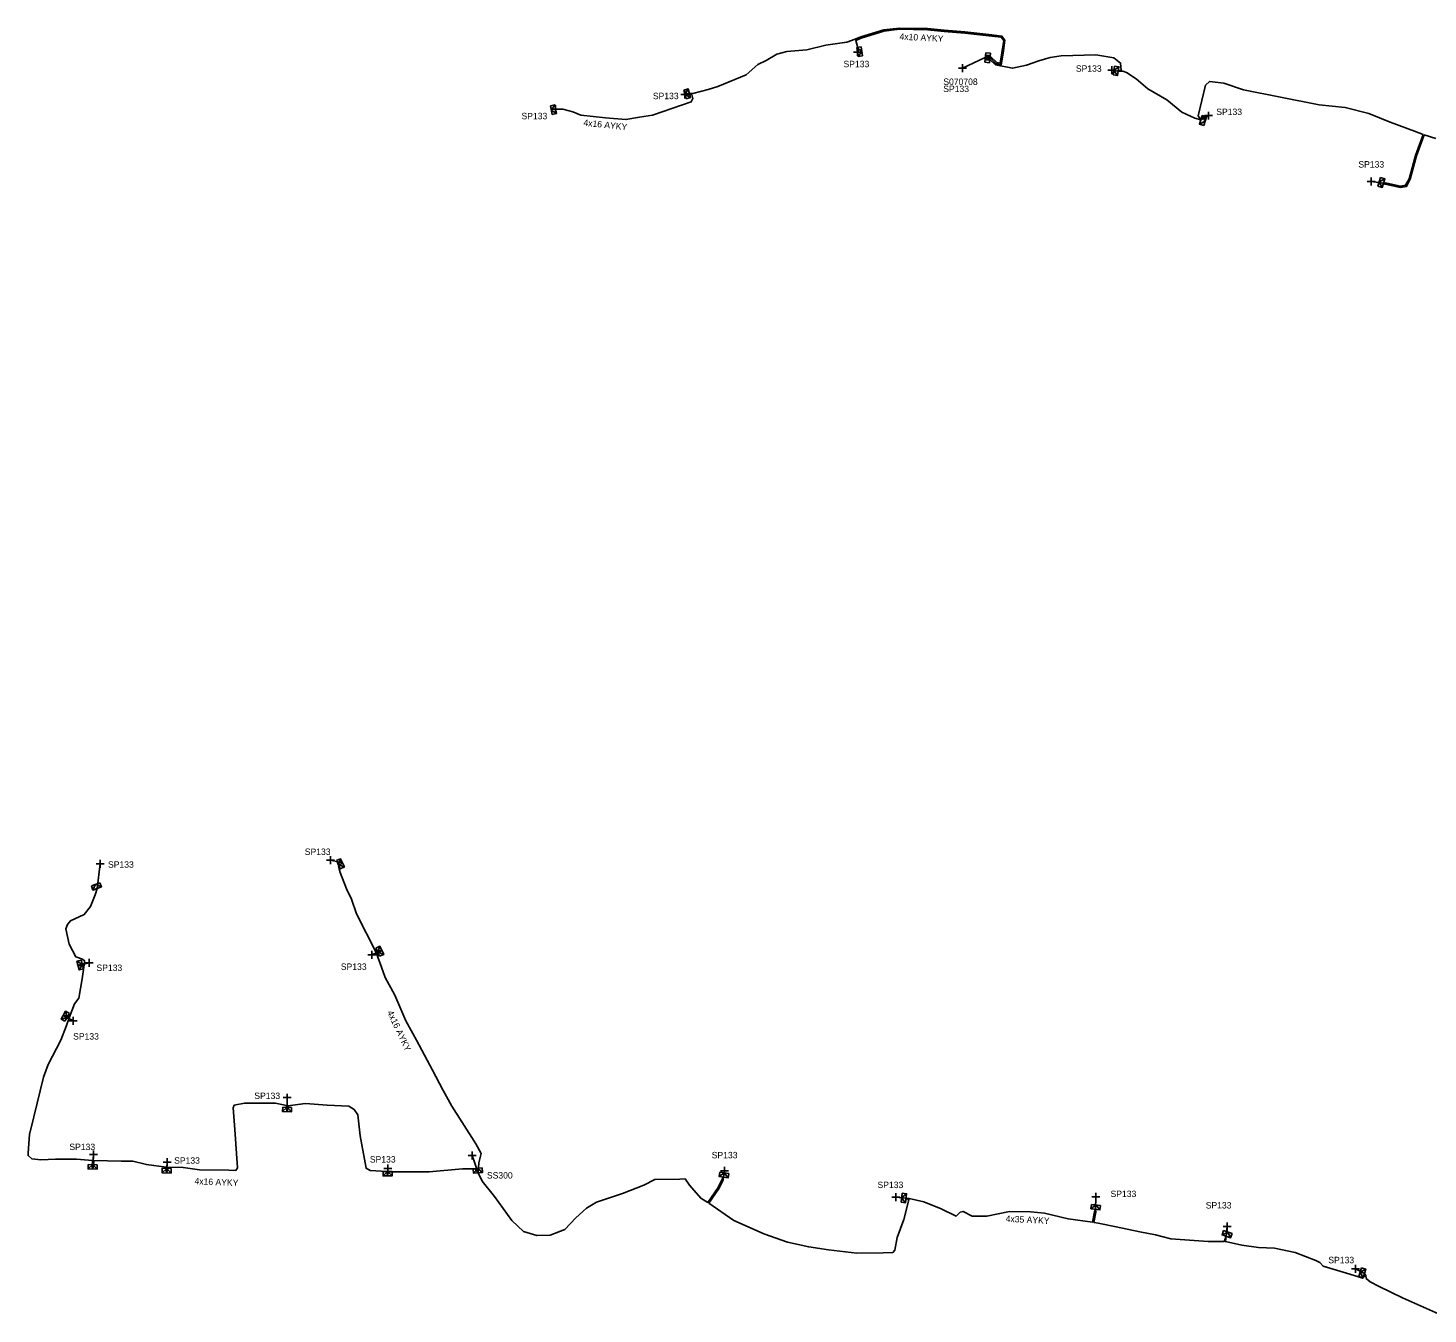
# Model space of a CAD drawing. Extents: x -763093 to -760976, y -1155572 to -1152009.
# Drawn here: x -763081 to -762862.9, y -1153648.9 to -1153448.5 of the extents above; entities that cross this region are included whole.
import ezdxf

# ---------------------------------------------------------------- set-up
doc = ezdxf.new("R2010")
doc.units = 0
for name, color, linetype in [('Vrstva 1', 7, 'Continuous'), ('Vrstva 28', 7, 'Continuous'), ('Vrstva 29', 7, 'Continuous'), ('Vrstva 30', 7, 'Continuous'), ('Vrstva 31', 7, 'Continuous'), ('Vrstva 33', 7, 'Continuous'), ('Vrstva 34', 7, 'Continuous'), ('Vrstva 5', 7, 'Continuous'), ('Vrstva 52', 7, 'Continuous'), ('Vrstva 54', 7, 'Continuous'), ('Vrstva 59', 7, 'Continuous'), ('Vrstva 6', 7, 'Continuous'), ('Vrstva 8', 7, 'Continuous'), ('Vrstva 9', 7, 'Continuous')]:
    doc.layers.add(name, color=color, linetype=linetype)

# ---------------------------------------------------------------- blocks, each defined once
blk = doc.blocks.new('NN800')
at = {"layer": 'Vrstva 1'}
for points in [[(-0.44, 0.44), (0.44, -0.44)], [(-0.44, -0.44), (0.44, 0.44)]]:
    blk.add_lwpolyline(points, dxfattribs=at)
blk = doc.blocks.new('NN620')
at = {"layer": 'Vrstva 8'}
for points in [[(0.75, 0), (-0.75, 0)], [(-0.75, 0), (-0.75, -0.75)], [(0.75, -0.75), (0.75, 0)], [(-0.75, -0.75), (0.75, -0.75)], [(0.37, -0.18), (-0.38, -0.18)], [(-0.38, -0.18), (-0.38, -0.56)], [(-0.38, -0.56), (0.37, -0.56)], [(0.32, -0.23), (-0.33, -0.23)], [(-0.33, -0.23), (-0.33, -0.51)], [(-0.33, -0.51), (0.32, -0.51)], [(0.27, -0.27), (-0.28, -0.27)], [(-0.28, -0.27), (-0.28, -0.46)], [(-0.28, -0.46), (0.27, -0.46)], [(0.23, -0.32), (-0.23, -0.32)], [(-0.23, -0.32), (-0.23, -0.42)], [(-0.23, -0.42), (0.23, -0.42)], [(-0.19, -0.37), (0.19, -0.37)], [(0.23, -0.42), (0.23, -0.32)], [(0.27, -0.46), (0.27, -0.27)], [(0.32, -0.51), (0.32, -0.23)], [(0.37, -0.56), (0.37, -0.18)]]:
    blk.add_lwpolyline(points, dxfattribs=at)
blk = doc.blocks.new('NN630')
at = {"layer": 'Vrstva 9'}
for points in [[(0, -0.7), (-0.7, 0)], [(-0.7, -0.7), (-0.7, 0), (0.7, 0), (0.7, -0.7)], [(-0.7, -0.7), (0.7, -0.7)], [(0, -0.7), (0.7, 0)]]:
    blk.add_lwpolyline(points, dxfattribs=at)

msp = doc.modelspace()

# ---------------------------------------------------------------- linework, layer by layer
at = {"layer": 'Vrstva 5'}
for points in [[(-762931.07, -1153453.19), (-762930.16, -1153454.05), (-762929.37, -1153454.21), (-762929.06, -1153452.4), (-762928.79, -1153450.38), (-762929.28, -1153449.75), (-762930.82, -1153449.56), (-762935.05, -1153449.08), (-762938.25, -1153448.81), (-762940.86, -1153448.58), (-762945.22, -1153448.48), (-762947.69, -1153448.75), (-762951.27, -1153449.86), (-762952.11, -1153450.24), (-762953.44, -1153450.68), (-762956.69, -1153451.17), (-762959.69, -1153451.89), (-762962.76, -1153452.14), (-762964.36, -1153452.58), (-762965.98, -1153453.56), (-762967.3, -1153454.18), (-762969.12, -1153455.76), (-762973.54, -1153457.62), (-762975.04, -1153458.08), (-762977.41, -1153458.69), (-762977.97, -1153458.66)], [(-762861.65, -1153465.71), (-762863.46, -1153465.15), (-762864.64, -1153468.4), (-762865.64, -1153472.04), (-762866.22, -1153473.17), (-762867.16, -1153473.31), (-762869.54, -1153472.82), (-762869.8, -1153472.66), (-762869.51, -1153472.62), (-762867.16, -1153473.11), (-762866.36, -1153472.99), (-762865.82, -1153471.96), (-762864.84, -1153468.34), (-762863.65, -1153465.08), (-762864.98, -1153464.54), (-762868.79, -1153463.13), (-762872.07, -1153461.79), (-762875.79, -1153460.85), (-762879.82, -1153460.46), (-762885.84, -1153459.27), (-762891.63, -1153458.09), (-762894.67, -1153457.09), (-762896.93, -1153456.81), (-762897.52, -1153457.38), (-762898.67, -1153462.16), (-762898.27, -1153462.79), (-762899.18, -1153462.52), (-762901.25, -1153461.62), (-762903.58, -1153459.69), (-762906.53, -1153457.94), (-762908.34, -1153456.41), (-762909.87, -1153455.42), (-762910.45, -1153455.22), (-762911.13, -1153455.21), (-762910.68, -1153455.05), (-762910.78, -1153453.95), (-762911.83, -1153453.15), (-762914.64, -1153452.64), (-762920.01, -1153452.82), (-762921.76, -1153453.1), (-762923.53, -1153453.58), (-762925.45, -1153454.26), (-762927.61, -1153454.75), (-762930.26, -1153454.23), (-762931.1, -1153453.43)], [(-763010.89, -1153626.87), (-763010.79, -1153625.3), (-763010.39, -1153623.85), (-763011.25, -1153622.34), (-763011.49, -1153621.95), (-763015.01, -1153616.5), (-763016.37, -1153613.94), (-763017.99, -1153610.86), (-763020.5, -1153606.21), (-763022.17, -1153603.21), (-763023.89, -1153599.19), (-763025.37, -1153596.41), (-763025.92, -1153594.82), (-763026.7, -1153592.71), (-763026.26, -1153592.5), (-763025.89, -1153592.2), (-763026.35, -1153592.31), (-763026.79, -1153592.53), (-763029.82, -1153586.53), (-763030.6, -1153584.21), (-763031.39, -1153582.6), (-763032.41, -1153580.05), (-763032.62, -1153579.11), (-763032.03, -1153578.56)], [(-763070.25, -1153582.57), (-763070.58, -1153583.55), (-763071.3, -1153585.38), (-763072.27, -1153586.61), (-763074.41, -1153587.58), (-763074.89, -1153588.17), (-763075.12, -1153588.83), (-763074.6, -1153591.22), (-763073.6, -1153593.2), (-763072.54, -1153593.56), (-763072.2, -1153593.83), (-763072.25, -1153594.23), (-763072.86, -1153594.39), (-763073.22, -1153594.58), (-763072.81, -1153594.59), (-763072.28, -1153594.45), (-763072.6, -1153596.65), (-763073.12, -1153599.63), (-763073.77, -1153600.55), (-763074.6, -1153602.71), (-763075.13, -1153602.42), (-763075.54, -1153602.31), (-763075.23, -1153602.59), (-763074.67, -1153602.9), (-763075.02, -1153603.89), (-763075.93, -1153606.22), (-763077.87, -1153610), (-763078.63, -1153611.98), (-763080.14, -1153618.14), (-763080.78, -1153620.91), (-763081.03, -1153623.74), (-763081.01, -1153624.19), (-763080.42, -1153624.67), (-763079.03, -1153624.84), (-763076.77, -1153624.76), (-763073.46, -1153624.73), (-763070.97, -1153624.94), (-763071.03, -1153625.89), (-763070.96, -1153626.29), (-763070.83, -1153625.91), (-763070.77, -1153624.95), (-763066.5, -1153625.08), (-763064.67, -1153625.06), (-763062.58, -1153625.58), (-763059.48, -1153625.99), (-763059.5, -1153626.49), (-763059.43, -1153626.88), (-763059.29, -1153626.47), (-763059.28, -1153626), (-763056.83, -1153626.06), (-763054.28, -1153626.38), (-763049.72, -1153626.44), (-763048.65, -1153626.51), (-763048.37, -1153626.1), (-763048.8, -1153620.11), (-763049.08, -1153616.76), (-763048.92, -1153616.35), (-763047.28, -1153616.01), (-763042.44, -1153616.03), (-763040.75, -1153616.4), (-763040.76, -1153616.89), (-763040.66, -1153617.35), (-763040.55, -1153616.88), (-763040.55, -1153616.41), (-763037.81, -1153616.07), (-763034.4, -1153616.31), (-763031.02, -1153616.5), (-763030.18, -1153617.01), (-763029.65, -1153617.85), (-763029.26, -1153621.12), (-763028.36, -1153626.15), (-763027.72, -1153626.49), (-763025.09, -1153626.69), (-763024.99, -1153627.35), (-763024.89, -1153626.7), (-763018.54, -1153626.73), (-763013.34, -1153626.27), (-763011.41, -1153626.27), (-763010.89, -1153626.87)], [(-763010.89, -1153626.87), (-763010.26, -1153628.18), (-763008.33, -1153630.56), (-763005.63, -1153634.31), (-763003.82, -1153636.01), (-763001.72, -1153636.64), (-762999.65, -1153636.58), (-762997.37, -1153635.72), (-762995.64, -1153633.87), (-762994.02, -1153632.38), (-762992.44, -1153631.43), (-762988.41, -1153630.08), (-762985.07, -1153628.82), (-762983.33, -1153627.92), (-762979.46, -1153627.84), (-762978.65, -1153627.81), (-762977.96, -1153628.77), (-762976.19, -1153630.83), (-762975.09, -1153631.48), (-762973.5, -1153629.14), (-762972.86, -1153627.86), (-762972.63, -1153627.56), (-762972.71, -1153627.97), (-762973.32, -1153629.24), (-762974.92, -1153631.59), (-762971.03, -1153634.32), (-762968.83, -1153635.29), (-762966.36, -1153636.4), (-762962.68, -1153637.69), (-762959.38, -1153638.42), (-762956.3, -1153638.88), (-762951.88, -1153639.4), (-762947.77, -1153639.33), (-762946.24, -1153639.28), (-762945.96, -1153638.93), (-762945.57, -1153636.97), (-762944.56, -1153634.16), (-762943.77, -1153631.08), (-762944.21, -1153630.83), (-762943.71, -1153630.88), (-762941.42, -1153631.4), (-762938.73, -1153632.5), (-762936.41, -1153633.62), (-762935.78, -1153633.01), (-762935.32, -1153632.88), (-762933.9, -1153633.6), (-762931.61, -1153633.61), (-762928.08, -1153632.91), (-762924.82, -1153632.94), (-762922.64, -1153633.18), (-762918.96, -1153634.05), (-762915.13, -1153634.56), (-762914.86, -1153632.93), (-762914.7, -1153632.56), (-762914.65, -1153632.98), (-762914.93, -1153634.59), (-762914.28, -1153634.72), (-762911.47, -1153635.31), (-762907.79, -1153636.05), (-762905.31, -1153636.51), (-762902.95, -1153637.14), (-762897.15, -1153637.57), (-762894.63, -1153637.56), (-762894.3, -1153636.76), (-762894.43, -1153637.58), (-762891.86, -1153638.16), (-762889.27, -1153638.49), (-762886.8, -1153638.59), (-762883.59, -1153639.28), (-762880.37, -1153640.55), (-762879.74, -1153640.85), (-762879.22, -1153641.4), (-762875.56, -1153642.51), (-762873.03, -1153643.29), (-762872.73, -1153642.99), (-762872.78, -1153642.56), (-762872.56, -1153642.88), (-762872.5, -1153643.33), (-762871.9, -1153643.86), (-762870.49, -1153644.58), (-762866.86, -1153646.33), (-762861.25, -1153648.87)]]:
    msp.add_lwpolyline(points, dxfattribs=at)
at = {"layer": 'Vrstva 52'}
for points in [[(-762931.04, -1153452.94), (-762930.06, -1153453.87), (-762929.53, -1153453.97), (-762929.26, -1153452.36), (-762928.99, -1153450.44), (-762929.38, -1153449.93), (-762930.84, -1153449.76), (-762935.07, -1153449.28), (-762938.27, -1153449.01), (-762940.88, -1153448.78), (-762945.22, -1153448.68), (-762947.65, -1153448.95), (-762951.19, -1153450.04), (-762952.04, -1153450.43), (-762951.62, -1153451.92), (-762951.78, -1153452.22)], [(-762977.97, -1153458.66), (-762977.59, -1153458.85), (-762977.43, -1153459.44), (-762977.67, -1153459.99), (-762983.71, -1153462.05), (-762985.76, -1153462.4), (-762987.87, -1153462.76), (-762991.05, -1153462.47), (-762994.89, -1153462.08), (-762996.13, -1153461.56), (-762997.69, -1153461.13), (-762998.81, -1153461.14)]]:
    msp.add_lwpolyline(points, dxfattribs=at)
at = {"layer": 'Vrstva 59'}
for points in [[(-762931.86, -1153453.07), (-762935.43, -1153454.75)], [(-762911.13, -1153455.21), (-762912.12, -1153455.06)], [(-762977.97, -1153458.66), (-762978.66, -1153458.84)], [(-762898.27, -1153462.79), (-762897.07, -1153462.14)], [(-762869.8, -1153472.66), (-762871.75, -1153472.38)], [(-763070.25, -1153582.57), (-763069.8, -1153578.73)], [(-763032.03, -1153578.56), (-763033.91, -1153578.17)], [(-763025.89, -1153592.2), (-763027.45, -1153592.92)], [(-763073.22, -1153594.58), (-763071.49, -1153594.17)], [(-763075.54, -1153602.31), (-763073.97, -1153603.19)], [(-763040.66, -1153617.35), (-763040.63, -1153615.16)], [(-763070.96, -1153626.29), (-763070.82, -1153624.03)], [(-763059.43, -1153626.88), (-763059.36, -1153625.2)], [(-763010.89, -1153626.87), (-763011.81, -1153624.17)], [(-763024.99, -1153627.35), (-763024.95, -1153626.19)], [(-762972.63, -1153627.56), (-762972.48, -1153626.57)], [(-762944.21, -1153630.83), (-762945.81, -1153630.64)], [(-762914.7, -1153632.56), (-762914.65, -1153630.61)], [(-762894.3, -1153636.76), (-762894.16, -1153635.26)], [(-762872.78, -1153642.56), (-762874.16, -1153641.81)]]:
    msp.add_lwpolyline(points, dxfattribs=at)

# ---------------------------------------------------------------- block references
at = {"layer": 'Vrstva 28', "rotation": -96.058988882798}
msp.add_blockref('NN620', (-762931.11, -1153453.15), dxfattribs=at)
at = {"layer": 'Vrstva 31'}
for p, rotation in [((-762951.78, -1153452.22), 97.74262177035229), ((-762911.13, -1153455.21), -98.5476083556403), ((-762977.97, -1153458.66), -74.71133610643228), ((-762998.81, -1153461.14), -79.27711111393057), ((-762898.27, -1153462.79), 71.93709721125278), ((-762869.8, -1153472.66), -106.94922508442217), ((-763032.03, -1153578.56), -65.16690551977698), ((-763070.25, -1153582.57), -159.9750974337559), ((-763025.89, -1153592.2), -65.20306386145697), ((-763073.22, -1153594.58), 105.30186963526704), ((-763075.54, -1153602.31), 60.45757780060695), ((-763040.66, -1153617.35), 178.64347584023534), ((-763070.96, -1153626.29), 177.5654222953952), ((-763059.43, -1153626.88), 177.53718345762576), ((-763024.99, -1153627.35), 179.56890294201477), ((-763010.89, -1153626.87), -174.67288613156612), ((-762972.63, -1153627.56), 171.51839442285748), ((-762944.21, -1153630.83), -96.68386385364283), ((-762914.7, -1153632.56), 173.44779451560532), ((-762894.3, -1153636.76), 161.4816499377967), ((-762872.78, -1153642.56), -107.04471941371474)]:
    msp.add_blockref('NN630', p, dxfattribs=dict(at, rotation=rotation))
at = {"layer": 'Vrstva 34'}
for p, rotation in [((-762951.78, -1153452.22), 44.99999995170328), ((-762935.43, -1153454.75), 45), ((-762912.12, -1153455.06), 45), ((-762978.66, -1153458.84), 45), ((-762998.81, -1153461.14), 45), ((-762897.07, -1153462.14), 45), ((-762871.75, -1153472.38), 45), ((-763069.8, -1153578.73), 45), ((-763033.91, -1153578.17), 45), ((-763027.45, -1153592.92), 45), ((-763071.49, -1153594.17), 45), ((-763073.97, -1153603.19), 45.00000009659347), ((-763040.63, -1153615.16), 45), ((-763070.82, -1153624.03), 45), ((-763059.36, -1153625.2), 44.99999995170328), ((-763011.81, -1153624.17), 45), ((-763024.95, -1153626.19), 45), ((-762972.48, -1153626.57), 44.99999995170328), ((-762945.81, -1153630.64), 45), ((-762914.65, -1153630.61), 44.99999995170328), ((-762894.16, -1153635.26), 45), ((-762874.16, -1153641.81), 45)]:
    msp.add_blockref('NN800', p, dxfattribs=dict(at, rotation=rotation))

# ---------------------------------------------------------------- texts
at = {"layer": 'Vrstva 29'}
msp.add_text('S070708', height=1, dxfattribs=at).set_placement((-762938.4, -1153457.35))
at = {"layer": 'Vrstva 30'}
msp.add_text('SP133', height=1, dxfattribs=at).set_placement((-762938.41, -1153458.46))
at = {"layer": 'Vrstva 33'}
for s, p in [('SP133', (-762953.95, -1153454.59)), ('SP133', (-762917.74, -1153455.3)), ('SP133', (-762983.66, -1153459.57)), ('SP133', (-763004.13, -1153462.7)), ('SP133', (-762895.86, -1153462.04)), ('SP133', (-762873.72, -1153470.23)), ('SP133', (-763037.9, -1153577.34)), ('SP133', (-763068.56, -1153579.33)), ('SP133', (-763070.36, -1153595.42)), ('SP133', (-763032.28, -1153595.25)), ('SP133', (-763074, -1153606.11)), ('SP133', (-763045.76, -1153615.37)), ('SP133', (-763074.58, -1153623.33)), ('SP133', (-763058.26, -1153625.45)), ('SP133', (-763027.76, -1153625.27)), ('SP133', (-762974.49, -1153624.61)), ('SS300', (-763009.52, -1153627.76)), ('SP133', (-762948.65, -1153629.25)), ('SP133', (-762912.34, -1153630.65)), ('SP133', (-762897.51, -1153632.43)), ('SP133', (-762878.4, -1153640.96))]:
    msp.add_text(s, height=1, dxfattribs=at).set_placement(p)
at = {"layer": 'Vrstva 54'}
for s, rotation, p in [('4x10 AYKY', 356.917, (-762945.24, -1153450.29)), ('4x16 AYKY', 353.909, (-762994.51, -1153463.7))]:
    msp.add_text(s, height=1, rotation=rotation, dxfattribs=at).set_placement(p)
at = {"layer": 'Vrstva 6'}
for s, rotation, p in [('4x16 AYKY', 295.156, (-763025.11, -1153601.85)), ('4x16 AYKY', 357.439, (-763055.1, -1153628.65)), ('4x35 AYKY', 357.194, (-762928.7, -1153634.51))]:
    msp.add_text(s, height=1, rotation=rotation, dxfattribs=at).set_placement(p)

doc.saveas('drawing.dxf')
